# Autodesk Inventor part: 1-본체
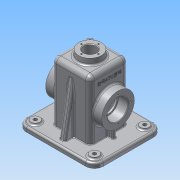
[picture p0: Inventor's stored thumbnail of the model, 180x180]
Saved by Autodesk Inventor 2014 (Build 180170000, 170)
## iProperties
Created: 2015-12
Part Number: 1-본체
Material: 알루미늄 6061
Document SubType Name: Modeling
Designer: Administrator
Density: 2.71 g/cm^3
Appearance: 알루미늄 - 평지
Mass: 859.371 g
Surface Area: 914.736 cm^2
Volume: 317.111 cm^3
Author: Administrator
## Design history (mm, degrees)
sketch "스케치1"
  geometry: L1 (-50, 57.5)-(50, 57.5); L2 (65, 42.5)-(65, -42.5); L3 (50, -57.5)-(-50, -57.5); L4 (-65, -42.5)-(-65, 42.5); L5 (-65, 57.5)-(65, -57.5); L6 (65, 57.5)-(-65, -57.5); A1 r 15 centre (-50, 42.5) between (-50, 57.5) and (-65, 42.5); A2 r 15 centre (-50, -42.5) between (-65, -42.5) and (-50, -57.5); A3 r 15 centre (50, -42.5) between (50, -57.5) and (65, -42.5); A4 r 15 centre (50, 42.5) between (65, 42.5) and (50, 57.5); 1 further point
  constraints: 12 end point, 8 point on circle, 8 point on line, 8 tangent, 4 centre point, 3 equal radius, 2 midpoint, 2 parallel, 1 horizontal, 1 perpendicular
  dimensions: "d0" = 130 distance of L5.start L6.start; "d1" = 115 distance of L6.start L5.end; "d2" = 15 radius of A1
extrude "돌출1" new body sketch "스케치1" distance "d3" = 8; taper "d4" = 0 deg
sketch "스케치2"
  geometry: L1 (50, 57.5)-(-50, 57.5) reference; L2 (-65, 42.5)-(-65, -42.5) reference; L3 (-50, -57.5)-(50, -57.5) reference; L4 (65, -42.5)-(65, 42.5) reference; L5 (-50, 52.5)-(50, 52.5); L6 (60, 42.5)-(60, -42.5); L7 (50, -52.5)-(-50, -52.5); L8 (-60, -42.5)-(-60, 42.5); A1 r 15 centre (-50, 42.5) between (-50, 57.5) and (-65, 42.5) reference; A2 r 15 centre (-50, -42.5) between (-65, -42.5) and (-50, -57.5) reference; A3 r 15 centre (50, -42.5) between (50, -57.5) and (65, -42.5) reference; A4 r 15 centre (50, 42.5) between (65, 42.5) and (50, 57.5) reference; A5 r 10 centre (50, 42.5) between (60, 42.5) and (50, 52.5); A6 r 10 centre (50, -42.5) between (50, -52.5) and (60, -42.5); A7 r 10 centre (-50, -42.5) between (-60, -42.5) and (-50, -52.5); A8 r 10 centre (-50, 42.5) between (-50, 52.5) and (-60, 42.5); 1 further point
  constraints: 8 end point, 8 point on circle, 4 centre point, 7 other
  dimensions: "d5" = 5 distance between parallel lines of L8 L2
extrude "돌출2" join sketch "스케치2" distance "d6" = 2; taper "d7" = 0 deg
sketch "스케치3"
  geometry: L1 (-32.5, 32.5)-(32.5, 32.5); L2 (32.5, 32.5)-(32.5, -32.5); L3 (32.5, -32.5)-(-32.5, -32.5); L4 (-32.5, -32.5)-(-32.5, 32.5); L5 (-32.5, 32.5)-(32.5, -32.5); L6 (32.5, 32.5)-(-32.5, -32.5); 1 further point
  constraints: 12 end point, 2 midpoint, 2 parallel, 2 perpendicular, 1 horizontal
  dimensions: "d8" = 65 distance of L1.start L1.end
extrude "돌출3" join sketch "스케치3" distance "d9" = 100; taper "d10" = 0 deg
sketch "스케치4"
  geometry: C1 r 20 at (0, 0); 1 further point
  constraints: 1 centre point, 1 coincident
  dimensions: "d11" = 40 diameter of C1
extrude "돌출4" join sketch "스케치4" distance "d12" = 10; taper "d13" = -5 deg
hole "구멍1" diameter "d16" = 21; stored, may be unused: countersink angle "d20" = 90 deg, drill point angle "d22" = 118 deg; dims "d14" = 10, "d15" = 10, "d17" = 6, "d18" = 4, "d19" = 2, "d21" = 8
fillet "모깎기1" dims "d23" = 8
node "작업 평면1"
sketch "스케치5"
  geometry: L1 (-10, -18)-(-10, 67) reference; C1 r 27.5 at (45, 24.5); 2 further points
  constraints: 1 centre point, 1 horizontal alignment, 1 midpoint
  dimensions: "d25" = 55 diameter of C1; "d26" = 55 distance from line of C1.centre L1
extrude "돌출5" join sketch "스케치5" stored distance "d27" = 10; taper "d28" = 0 deg
hole "구멍2" diameter "d31" = 35; stored, may be unused: countersink angle "d35" = 90 deg, drill point angle "d37" = 0 deg; dims "d32" = 6, "d33" = 4, "d34" = 2, "d36" = 17, "d125" = 10, "d126" = 10
sketch "스케치6"
  geometry: C1 r 17.5 at (0, 0) reference; C2 r 27.5 at (0, 0) reference; A1 r 21 centre (0, 0) between (21, 0) and (-21, 0); 3 further points
  constraints: 4 point on circle, 2 horizontal alignment, 2 vertical alignment, 1 centre point, 1 coincident
  dimensions: "d38" = 42 diameter of A1
hole "구멍3" sketch "스케치6" at (21, 0), (-21, 0), (0, 21), (0, -21) diameter "d39" = 3.242; stored, may be unused: countersink angle "d43" = 90 deg, drill point angle "d45" = 118 deg; dims "d40" = 8, "d41" = 4, "d42" = 2, "d44" = 10
sketch "스케치7"
  geometry: L1 (-24.5, 27.5)-(24.5, 27.5); L2 (27.5, 24.5)-(27.5, -24.5); L3 (24.5, -27.5)-(-24.5, -27.5); L4 (-27.5, -24.5)-(-27.5, 24.5); L5 (-27.5, 27.5)-(27.5, -27.5); L6 (27.5, 27.5)-(-27.5, -27.5); C1 r 10.5 at (0, 0) reference; A1 r 3 centre (-24.5, 24.5) between (-24.5, 27.5) and (-27.5, 24.5); A2 r 3 centre (24.5, 24.5) between (27.5, 24.5) and (24.5, 27.5); A3 r 3 centre (24.5, -24.5) between (24.5, -27.5) and (27.5, -24.5); A4 r 3 centre (-24.5, -24.5) between (-27.5, -24.5) and (-24.5, -27.5)
  constraints: 12 end point, 8 point on circle, 8 point on line, 8 tangent, 4 centre point, 3 equal radius, 2 midpoint, 2 parallel, 2 perpendicular, 1 horizontal
  dimensions: "d46" = 55 distance of L5.start L6.start; "d47" = 3 radius of A1
extrude "돌출6" cut sketch "스케치7" distance "d48" = 105; taper "d49" = 0 deg
node "작업 평면2"
sketch "스케치8"
  geometry: L1 (100, -8)-(0, -8) reference; L2 (100, -18)-(100, -33) reference; L3 (100, 67)-(100, -18) reference; L4 (100, 82)-(100, 67) reference; L5 (0, 57)-(100, 57) reference; L6 (108, 67)-(108, 82) reference; L7 (100, 72)-(14.931, 57); L8 (108, 82)-(100, 82) reference; 1 further point
  constraints: 2 end point, 2 point on line
  dimensions: "d51" = 10 vertical distance of L6.end L7.start; "d52" = 10 deg angle of L7 L8
extrude "돌출7" join sketch "스케치8" stored distance "d53" = 10; taper "d54" = 0 deg
fillet "모깎기2" dims "d55" = 3
fillet "모깎기3" dims "d56" = 3
node "작업 평면4"
sketch "스케치9"
  geometry: L1 (0, -8)-(-100, -8) reference; L2 (-100, -33)-(-100, -18) reference; L3 (-100, -18)-(-100, 67) reference; L4 (-108, -33)-(-100, -33) reference; L5 (-110, -18)-(-110, -28) reference; L6 (-100, -23)-(-14.931, -8); 1 further point
  constraints: 2 end point, 2 point on line
  dimensions: "d57" = 10 vertical distance of L4.start L6.start; "d58" = 10 deg angle of L4 L6
extrude "돌출8" join sketch "스케치9" stored distance "d59" = 10; taper "d60" = 0 deg
fillet "모깎기4" dims "d61" = 3
fillet "모깎기5" dims "d62" = 3
node "작업 평면5"
sketch "스케치10"
  geometry: L1 (-25.5, 100)-(74.5, 100) reference; L2 (74.5, 100)-(89.5, 100) reference; L3 (57, 100)-(57, 67.49) reference; L4 (57, 82.5)-(72, 82.5) reference; L5 (-8, 67.49)-(-8, 100) reference; L6 (-40.5, 100)-(-25.5, 100) reference; L7 (-40.5, 108)-(-40.5, 100) reference; L8 (89.5, 108)-(89.5, 100) reference; L9 (-23, 82.5)-(-8, 82.5) reference; L10 (67, 100)-(67, 82.5); L11 (52, 110)-(52, 5) reference; L12 (-3, 110)-(-3, 5) reference; L13 (-18, 100)-(-18, 82.5); L14 (-18, 82.5)-(-18, 79.617); L15 (-18, 79.617)-(-8, 79.617); L16 (67, 82.5)-(67, 79.617); L17 (67, 79.617)-(57, 79.617); 1 further point
  constraints: 12 end point, 6 point on line, 4 perpendicular, 1 collinear, 1 parallel
  dimensions: "d64" = 15 horizontal distance of L10.start L11.start; "d65" = 15 horizontal distance of L12.start L13.start
extrude "돌출9" join sketch "스케치10" stored distance "d66" = 6; taper "d67" = 0 deg
sketch "스케치11"
  geometry: C1 r 7.5 at (-50, 42.5); C2 r 7.5 at (50, 42.5); C3 r 7.5 at (50, -42.5); C4 r 7.5 at (-50, -42.5); A1 r 15 centre (-50, 42.5) between (-50, 57.5) and (-65, 42.5) reference; A2 r 15 centre (-50, -42.5) between (-65, -42.5) and (-50, -57.5) reference; A3 r 15 centre (50, -42.5) between (50, -57.5) and (65, -42.5) reference; A4 r 15 centre (50, 42.5) between (65, 42.5) and (50, 57.5) reference; 1 further point
  constraints: 4 centre point, 4 coincident
  dimensions: "d68" = 15 diameter of C1; "d69" = 15 diameter of C4; "d70" = 15 diameter of C2; "d71" = 15 diameter of C3
extrude "돌출10" join sketch "스케치11" distance "d72" = 3; taper "d73" = 0 deg
sketch "스케치12"
  geometry: C1 r 10.5 at (0, 0) reference; C2 r 19.125 at (0, 0) reference; A1 r 14.5 centre (0, 0) between (0, 14.5) and (0, -14.5); 2 further points
  constraints: 4 point on circle, 2 horizontal alignment, 2 vertical alignment, 1 centre point, 1 coincident
  dimensions: "d74" = 29 diameter of A1
hole "구멍4" sketch "스케치12" at (0, 14.5), (0, -14.5), (14.5, 0), (-14.5, 0) diameter "d75" = 2.459; stored, may be unused: countersink angle "d79" = 90 deg, drill point angle "d81" = 118 deg; dims "d76" = 7, "d77" = 4, "d78" = 2, "d80" = 9
hole "구멍5" diameter "d84" = 6; stored, may be unused: countersink angle "d88" = 90 deg, drill point angle "d90" = 0 deg; dims "d82" = 10, "d83" = 10, "d85" = 7, "d86" = 4, "d87" = 2, "d89" = 9
hole "구멍6" diameter "d93" = 6; stored, may be unused: countersink angle "d97" = 90 deg, drill point angle "d99" = 0 deg; dims "d91" = 10, "d92" = 10, "d94" = 7, "d95" = 4, "d96" = 2, "d98" = 9
hole "구멍7" diameter "d102" = 6; stored, may be unused: countersink angle "d106" = 90 deg, drill point angle "d108" = 0 deg; dims "d100" = 10, "d101" = 10, "d103" = 7, "d104" = 4, "d105" = 2, "d107" = 9
hole "구멍8" diameter "d111" = 6; stored, may be unused: countersink angle "d115" = 90 deg, drill point angle "d117" = 0 deg; dims "d109" = 10, "d110" = 10, "d112" = 7, "d113" = 4, "d114" = 2, "d116" = 9
sketch "스케치13"
  geometry: L1 (0, -8)-(100, -8) reference; L2 (-10, 5.375)-(-10, 43.625) reference; 2 further points
  constraints: 1 other
  dimensions: "d118" = 32.5 distance from line of point (16, 24.5) L1; "d119" = 26 horizontal distance of point (16, 24.5) L2.end
feature "엠보싱1" sketch "스케치13" dims "d120" = 0.5, "d121" = 0
fillet "모깎기6" dims "d122" = 8
hole "구멍9" diameter "d127" = 30; stored, may be unused: countersink angle "d131" = 90 deg, drill point angle "d133" = 0 deg; dims "d123" = 10, "d124" = 10, "d128" = 7, "d129" = 4, "d130" = 2, "d132" = 9
fillet "모깎기7" dims "d134" = 3
fillet "모깎기8" dims "d135" = 3
fillet "모깎기9" dims "d136" = 1
chamfer "모따기1" distance "d137" = 1; stored, may be unused: second distance "d138" = 2, angle "d139" = 45 deg
fillet "모깎기10" dims "d140" = 3
fillet "모깎기11" dims "d141" = 0.3
node "솔리드1"
mirror "대칭1"
other parameters: "d24" = 15
